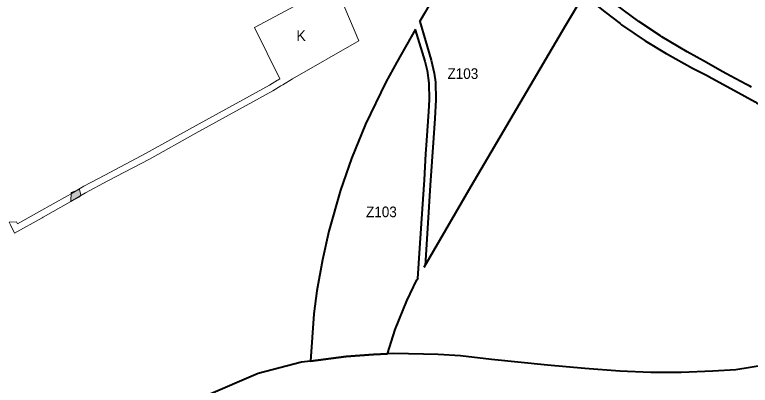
# Model space of a CAD drawing. Extents: x -650276 to -642489, y -1074425 to -1066658.
# Drawn here: x -648708 to -647044, y -1069023 to -1068186 of the extents above; entities that cross this region are included whole.
import ezdxf

# ---------------------------------------------------------------- set-up
doc = ezdxf.new("R2010")
doc.units = 0
doc.header["$LTSCALE"] = 9.6
for name, color, linetype, lineweight in [('1', 7, 'Continuous', 13), ('43', 7, 'Continuous', 13), ('44', 7, 'Continuous', 40), ('47', 7, 'Continuous', 13)]:
    doc.layers.add(name, color=color, linetype=linetype, lineweight=lineweight)

msp = doc.modelspace()

# ---------------------------------------------------------------- hatches: boundary and pattern name
at = {"layer": '1'}
msp.add_hatch(color=256, dxfattribs=at).paths.add_polyline_path([(-648561.49, -1068596.84), (-648558.08, -1068592.36), (-648560.79, -1068580.12), (-648579.97, -1068587.39), (-648580.66, -1068607.64)])

# ---------------------------------------------------------------- linework, layer by layer
msp.add_lwpolyline([(-648561.49, -1068596.84), (-648558.08, -1068592.36), (-648560.79, -1068580.12), (-648579.97, -1068587.39), (-648580.66, -1068607.64)], close=True, dxfattribs=at)
at = {"layer": '44'}
for points in [[(-647618.773, -1067899.914), (-647685.819, -1068016.861), (-647781.346, -1068183.485), (-647791.669, -1068201.583)], [(-647781.204, -1068756.329), (-647675.054, -1068572.919), (-647461.188, -1068209.373), (-647419.713, -1068138.871), (-647472.338, -1068093.096), (-647553.628, -1067999.427), (-647618.773, -1067899.915), (-647618.773, -1067899.914)], [(-647040.77, -1068349.4), (-647044.93, -1068347.08), (-647053.75, -1068342.11), (-647099.2, -1068318.27), (-647112.813, -1068310.564), (-647142.41, -1068293.81), (-647186.26, -1068269.45), (-647243.39, -1068235.26), (-647246.8, -1068233.08), (-647295.47, -1068201.09), (-647347.74, -1068162.54), (-647349.59, -1068163.24), (-647350.6, -1068160.26), (-647353.81, -1068157.67), (-647385.13, -1068131.51), (-647405.026, -1068113.904)], [(-647419.713, -1068138.871), (-647405.71, -1068151.74), (-647372.38, -1068179.01), (-647337.74, -1068205.67), (-647334.62, -1068208.02), (-647307.39, -1068227.44), (-647281.64, -1068244.34), (-647234.11, -1068273.04), (-647230.83, -1068274.93), (-647174.56, -1068306.35), (-647142.788, -1068322.462), (-647130.29, -1068328.8), (-647079.16, -1068357.01), (-647032.91, -1068382.51), (-647029.23, -1068384.46), (-646997.06, -1068401.37), (-646929.56, -1068435.42), (-646927.06, -1068436.66)], [(-647791.055, -1068200.507), (-647765.22, -1068287.94), (-647758.45, -1068317.66), (-647756.09, -1068337.61), (-647754.99, -1068378.21), (-647757.41, -1068419.98), (-647760.22, -1068463.96), (-647768.02, -1068570.36), (-647772.85, -1068656.41), (-647778.967, -1068752.463)], [(-647801.168, -1068218.237), (-647843.6, -1068292.629), (-647868.214, -1068337.803), (-647914.339, -1068432.512), (-647946.187, -1068510.254), (-647971.074, -1068581.98), (-647997.27, -1068674.747), (-648011.775, -1068739.718), (-648023.914, -1068809.332), (-648030.73, -1068861.213), (-648038.596, -1068968.281), (-647958.168, -1068957.73)], [(-647801.797, -1068219.339), (-647780.07, -1068290.53), (-647774.94, -1068311.47), (-647770.81, -1068340.29), (-647770.12, -1068377.5), (-647771.74, -1068404.5), (-647775.82, -1068469.74), (-647778.24, -1068499.95), (-647781.55, -1068558.38), (-647785.79, -1068623.98), (-647791.77, -1068713.23), (-647796.139, -1068781.67)], [(-647864.531, -1068951.823), (-647846.989, -1068896.545), (-647820.883, -1068832.117), (-647797.632, -1068784.713), (-647795.185, -1068780.485)], [(-646934.465, -1068940.759), (-646973.61, -1068963.135), (-647006.63, -1068977.08), (-647076.422, -1068988.18), (-647128.674, -1068991.167), (-647199.672, -1068994.255), (-647268.348, -1068994.255), (-647338.816, -1068991.19), (-647417.895, -1068984.986), (-647502.412, -1068977.157), (-647629.424, -1068964.608), (-647699.561, -1068956.635), (-647749.978, -1068953.416)], [(-647749.978, -1068953.416), (-647850.043, -1068951.099), (-647864.531, -1068951.823), (-647895.901, -1068953.392), (-647958.168, -1068957.73), (-648038.596, -1068968.281), (-648038.596, -1068968.281), (-648038.746, -1068968.301), (-648058.764, -1068970.927)], [(-647958.168, -1068957.73), (-647895.901, -1068953.392), (-647864.531, -1068951.823)], [(-648058.764, -1068970.927), (-648156.739, -1068996.273), (-648392.002, -1069097.554)]]:
    msp.add_lwpolyline(points, dxfattribs=at)
at = {"layer": '47'}
msp.add_line((-648108.158, -1068330.583), (-648112.198, -1068333.037), dxfattribs=at)
for points in [[(-648101.42, -1068344.28), (-648079.33, -1068330.03), (-647929.45, -1068244.16), (-647971.35, -1068144.48), (-647982.969, -1068116.575), (-648165.28, -1068214.465), (-648108.158, -1068330.583)], [(-648112.198, -1068333.037), (-648112.92, -1068333.424), (-648131.034, -1068344.388), (-648305.242, -1068440.3), (-648410.111, -1068498.408), (-648503.768, -1068547.914), (-648551.041, -1068573.16)], [(-648547.25, -1068588.14), (-648496.73, -1068561.16), (-648402.97, -1068511.6), (-648297.99, -1068453.43), (-648123.53, -1068357.38), (-648105.49, -1068346.46), (-648101.42, -1068344.28)], [(-648551.041, -1068573.16), (-648580.062, -1068590.087), (-648588.022, -1068594.571), (-648653.034, -1068631.191), (-648701.568, -1068658.36), (-648703.816, -1068653.711), (-648720.238, -1068654.205)], [(-648720.238, -1068654.205), (-648717.32, -1068660.24), (-648708.14, -1068679.23), (-648645.69, -1068644.27), (-648643.654, -1068643.123), (-648580.66, -1068607.64), (-648547.25, -1068588.14)]]:
    msp.add_lwpolyline(points, dxfattribs=at)

# ---------------------------------------------------------------- texts
at = {"layer": '43'}
msp.add_text('K', height=24, dxfattribs=at).set_placement((-648070.59, -1068244.82))
msp.add_text('K', height=24, dxfattribs=at).set_placement((-648070.59, -1068244.82))
at = {"layer": '44', "width": 0.95}
for p in [(-647728.595, -1068330.624), (-647728.595, -1068330.624), (-647912.849, -1068643.055)]:
    msp.add_text('Z103', height=24, dxfattribs=at).set_placement(p)

doc.saveas('drawing.dxf')
